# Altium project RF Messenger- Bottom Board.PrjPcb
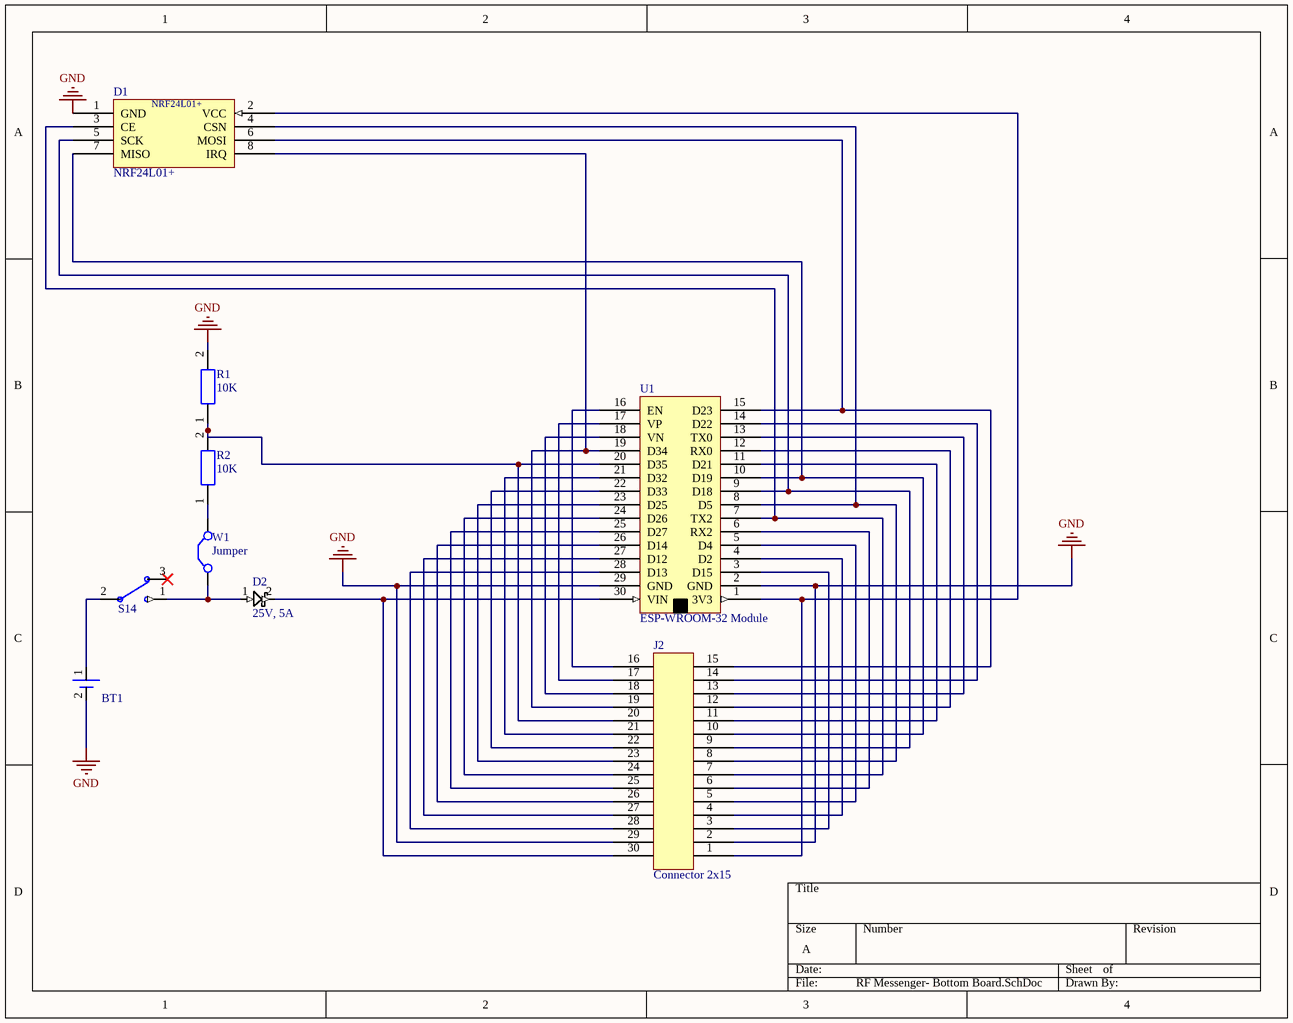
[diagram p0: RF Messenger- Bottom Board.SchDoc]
1 sheet, 9 parts. Net scope: global (net labels, ports and power ports of the same name join across sheets).
Board file: RF Messenger- Bottom Board.PcbDoc

## Sheet RF Messenger- Bottom Board.SchDoc
size A

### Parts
BT1  Battery  [BAT_BC3AAPC]  (value not drawn)
D1  NRF24L01+  [WRL-00705]
D2  25V, 5A  [CSHD5-25L]
J2  Connector 2x15  [RF Messenger Connector Headers - duplicate]
R1  10K  [Resistor 1812_PAN-M]
R2  10K  [Resistor 1812_PAN-M]
S14  Switch 2  [EG1257 Slide Switch]  (value not drawn)
U1  ESP-WROOM-32 Module  [ESP32 Dev Module]
W1  Jumper  [JUMPER1.5x1.5]

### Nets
GND: BT1.2 D1.1(GND) J2.2 J2.29 R1.2 U1.2(GND) U1.29(GND)
NetBT1_1: BT1.1 S14.2
NetD1_2: D1.2(VCC) J2.1 U1.1(3V3)
NetD1_3: D1.3(CE) J2.7 U1.7(TX2)
NetD1_4: D1.4(CSN) J2.8 U1.8(D5)
NetD1_5: D1.5(SCK) J2.9 U1.9(D18)
NetD1_6: D1.6(MOSI) J2.15 U1.15(D23)
NetD1_7: D1.7(MISO) J2.10 U1.10(D19)
NetD1_8: D1.8(IRQ) J2.19 U1.19(D34)
NetD2_1: D2.1 S14.1 W1.1(C1)
NetD2_2: D2.2 J2.30 U1.30(VIN)
NetJ2_3: J2.3 U1.3(D15)
NetJ2_4: J2.4 U1.4(D2)
NetJ2_5: J2.5 U1.5(D4)
NetJ2_6: J2.6 U1.6(RX2)
NetJ2_11: J2.11 U1.11(D21)
NetJ2_12: J2.12 U1.12(RX0)
NetJ2_13: J2.13 U1.13(TX0)
NetJ2_14: J2.14 U1.14(D22)
NetJ2_16: J2.16 U1.16(EN)
NetJ2_17: J2.17 U1.17(VP)
NetJ2_18: J2.18 U1.18(VN)
NetJ2_20: J2.20 R1.1 R2.2 U1.20(D35)
NetJ2_21: J2.21 U1.21(D32)
NetJ2_22: J2.22 U1.22(D33)
NetJ2_23: J2.23 U1.23(D25)
NetJ2_24: J2.24 U1.24(D26)
NetJ2_25: J2.25 U1.25(D27)
NetJ2_26: J2.26 U1.26(D14)
NetJ2_27: J2.27 U1.27(D12)
NetJ2_28: J2.28 U1.28(D13)
NetR2_1: R2.1 W1.2(C2)

Not connected (* = marked no-connect by the designer): S14 3*

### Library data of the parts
BT1 = Battery: General Battery
D1 = NRF24L01+: Radio module
D2 = Diode - Schottky: Generic Schottky Diode
J2 = Connector 2x15: 15 Pin Connector
R1 R2 = Resistor
S14 = Switch 2: General Slide Switch
U1 = ESP-WROOM-32 Module: ESP32 module THT
W1 = Jumper: Jumper Wire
